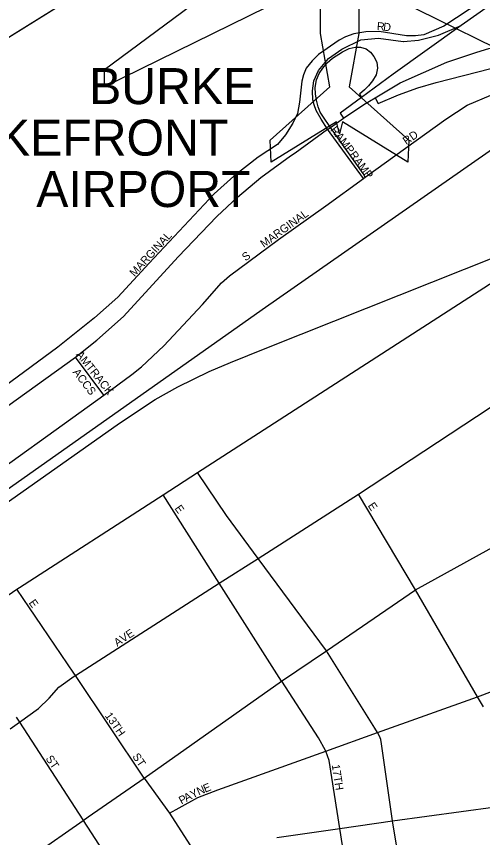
# Model space of a CAD drawing. Extents: x 2139079 to 2262683, y 1235796 to 1334992.
# Drawn here: x 2191123 to 2194033, y 1277243 to 1282370 of the extents above; entities that cross this region are included whole.
import ezdxf

# ---------------------------------------------------------------- set-up
doc = ezdxf.new("R2010")
doc.units = 0
for name, color, linetype in [('GM_X_Airport_Class_1', 7, 'Continuous'), ('GM_X_Airport_Text_Class_1', 7, 'Continuous'), ('GM_X_City_Street', 7, 'Continuous'), ('GM_X_City_Street_Text', 7, 'Continuous'), ('GM_X_Interchange_Ramps', 7, 'Continuous'), ('GM_X_Interstate_Route', 7, 'Continuous'), ('GM_X_Major_Lake', 7, 'Continuous'), ('GM_X_Rail_Line', 7, 'Continuous'), ('GM_X_State_Route', 7, 'Continuous'), ('GM_X_US_Route', 7, 'Continuous')]:
    doc.layers.add(name, color=color, linetype=linetype)

msp = doc.modelspace()

# ---------------------------------------------------------------- linework, layer by layer
at = {"layer": 'GM_X_Airport_Class_1'}
for points in [[(2193140.2, 1281637.8), (2193121.4, 1281711.9), (2192713.4, 1281459), (2192707.5, 1281596.6), (2193080.1, 1281930.7), (2193020, 1282263.2), (2193020, 1282593.4), (2191673.7, 1281929.9), (2191673.7, 1282039.4), (2192209.1, 1282435.3)], [(2194071.4, 1282435.3), (2194606.8, 1282039.4), (2194606.8, 1281929.9), (2193260.5, 1282593.4), (2193260.5, 1282263.2), (2193200.4, 1281930.7), (2193572.9, 1281596.6), (2193567.1, 1281459), (2193159, 1281711.9), (2193140.2, 1281637.8)]]:
    msp.add_lwpolyline(points, dxfattribs=at)
at = {"layer": 'GM_X_City_Street'}
for points in [[(2193289.3, 1281359), (2193299.7, 1281367.3), (2193552, 1281546.9), (2193802.9, 1281728.2), (2193935.7, 1281815.7), (2194084.6, 1281878.9), (2194378.3, 1281974.7), (2194463.9, 1282006.1), (2194512.4, 1282028.8), (2194561, 1282051.6), (2194694.7, 1282130.5), (2194996.1, 1282346.7), (2195257.9, 1282550.9), (2195383.5, 1282693.6), (2195668, 1283075.6), (2195903.1, 1283394.7), (2196027, 1283536.1), (2196119.5, 1283633.9), (2196406.7, 1283843.3), (2197904.1, 1284893.8)], [(2194028, 1282464.6), (2193791.3, 1282310.1), (2193665.2, 1282256), (2193614.3, 1282248.3), (2193557.1, 1282248.3), (2193387.2, 1282276.6), (2193303.9, 1282273.7), (2193229.2, 1282261.4), (2193177.5, 1282241.7), (2193138.1, 1282221.1), (2193008.9, 1282132.5), (2192968.9, 1282092.2), (2192931.5, 1282046.6), (2192913.9, 1282005.9), (2192904, 1281965.7), (2192888.9, 1281834.7), (2192877.3, 1281764.1), (2192847.8, 1281703.3), (2192803.5, 1281631), (2192752.5, 1281570.2), (2192632.7, 1281491.4), (2192479.5, 1281373.3), (2192356.3, 1281262), (2191951.6, 1280829.3), (2191755.3, 1280618), (2191609.8, 1280487.1), (2191381.7, 1280304.3), (2191048.3, 1280060)], [(2193539.5, 1282213.3), (2193631.9, 1282220.7), (2193756.7, 1282252.1), (2193898.6, 1282312.3)], [(2193289.3, 1281359), (2193065.3, 1281665), (2193024.3, 1281728), (2192994.7, 1281783.2), (2192981.2, 1281817.6), (2192972.3, 1281850.1), (2192971.5, 1281905), (2192978.6, 1281968.2), (2193007.5, 1282031.9), (2193071.9, 1282107.4), (2193153.3, 1282166), (2193271.8, 1282223), (2193383.6, 1282234.6), (2193536.3, 1282213.1), (2193539.5, 1282213.3)], [(2191475.2, 1279865.9), (2191669.4, 1280004.8), (2191844.2, 1280134.5), (2191903.5, 1280181.6), (2192042.6, 1280312.8), (2192283.9, 1280570.6), (2192404.1, 1280706.9), (2192452.6, 1280751.2), (2192759.3, 1280976.7), (2193054.8, 1281188.3), (2193289.3, 1281359)], [(2191143.3, 1278804.7), (2192038.6, 1279382.6), (2192253.8, 1279521.5), (2194362.9, 1280882.8)], [(2191484.2, 1278250.3), (2191491.2, 1278255.1), (2192389.5, 1278830.9), (2192631.9, 1278986.3), (2193257.9, 1279387.5), (2194159.3, 1279980.2), (2194716.7, 1280330.3), (2195137.4, 1280604.8), (2195175.8, 1280629.9), (2195293.5, 1280703), (2195567.4, 1280882.4)], [(2192078.6, 1277394.3), (2192139, 1277429.1), (2192255.8, 1277493.6), (2192381.1, 1277540.8), (2193054.4, 1277782.2), (2193377.5, 1277898), (2194000, 1278121.1), (2195091.4, 1278534.1), (2195674.4, 1278761.3), (2196370.6, 1279030.8), (2198889.4, 1280010.3), (2200879.8, 1280784.3)], [(2191669.4, 1280004.8), (2191491, 1280241.7)], [(2190067.4, 1278886.8), (2190180.5, 1278965), (2190501.9, 1279181.6), (2190975, 1279508.2), (2191475.2, 1279865.9)], [(2192631.9, 1278986.3), (2192435.2, 1279252.9), (2192253.8, 1279521.5)], [(2192778.8, 1278218.7), (2192778.4, 1278219.4), (2192389.5, 1278830.9), (2192038.6, 1279382.6)], [(2194037.4, 1278058.4), (2194000, 1278121.1), (2193613.8, 1278789.6), (2193257.9, 1279387.5)], [(2193100.7, 1278341.1), (2193058.9, 1278407.8), (2192631.9, 1278986.3)], [(2188798.9, 1277219.2), (2189624.1, 1277765.3), (2190085.9, 1278103.7), (2190750.5, 1278535.1), (2191125.4, 1278793.1), (2191143.3, 1278804.7)], [(2191481, 1278270), (2191125.4, 1278793.1)], [(2193771.5, 1275210.6), (2193775.7, 1275255.6), (2193780.2, 1275329.9), (2193778.7, 1275350.1), (2193770.9, 1275448.5), (2193694.2, 1275932), (2193670.2, 1276092.5), (2193597, 1276581.1), (2193469.6, 1277346.7), (2193402.6, 1277828.5), (2193397.8, 1277854.2), (2193390, 1277876.6), (2193377.5, 1277898), (2193360.8, 1277926.4), (2193100.7, 1278341.1)], [(2191083.8, 1277921.3), (2191141.9, 1277963.2), (2191259.9, 1278048.2), (2191327.4, 1278112.6), (2191387, 1278182.8), (2191484.2, 1278250.3)], [(2191921.2, 1277613.3), (2191491.2, 1278255.1), (2191481, 1278270)], [(2193141.7, 1277299.4), (2193075.2, 1277723.5), (2193054.4, 1277782.2), (2193053.2, 1277785.6), (2193009.1, 1277865.7), (2192778.8, 1278218.7)], [(2191120.8, 1277994), (2191141.9, 1277963.2), (2191537.6, 1277352.6)], [(2191537.6, 1277352.6), (2191539.9, 1277349.1), (2191834.9, 1276894.1)], [(2193262.9, 1276526.3), (2193141.7, 1277299.4)]]:
    msp.add_lwpolyline(points, dxfattribs=at)
at = {"layer": 'GM_X_Interchange_Ramps'}
for points in [[(2194741.1, 1282815.3), (2194699.3, 1282873.7), (2194248.3, 1282561.3), (2193898.6, 1282312.3), (2193475.2, 1282009.3), (2193277, 1281863.5), (2193144.2, 1281765.9), (2193164.5, 1281733.7)], [(2193299.7, 1281367.3), (2193287.2, 1281388.8), (2193083.5, 1281676), (2193035.2, 1281747), (2193019.5, 1281771.2), (2193006.8, 1281805.3), (2192996.8, 1281846.5), (2192989.7, 1281886.3), (2192988.3, 1281926.1), (2192996.8, 1281974.4), (2193012.6, 1282013.8), (2193034.8, 1282047.5), (2193062.7, 1282080.1), (2193096.1, 1282109.8), (2193159.3, 1282149.8), (2193200.8, 1282169.9), (2193238.3, 1282178.9), (2193271, 1282177.8), (2193306, 1282168.3), (2193332.8, 1282146.4), (2193353.9, 1282120.6), (2193372.1, 1282084.3), (2193376.1, 1282046.8), (2193369.3, 1282005.2), (2193346.4, 1281967.7), (2193319.6, 1281935.9), (2193295.4, 1281912.5), (2193263.6, 1281884.9), (2193277, 1281863.5)], [(2193361.5, 1281862.5), (2193380.8, 1281825.6), (2193507, 1281880.8), (2193627.7, 1281924), (2193743.3, 1281956.9), (2194336.8, 1282108.6), (2194393, 1282114.3), (2194424.6, 1282110.1), (2194457.7, 1282098), (2194485.5, 1282069.1), (2194512.4, 1282028.8), (2194527.1, 1282007), (2194571.9, 1282035.8)]]:
    msp.add_lwpolyline(points, dxfattribs=at)
at = {"layer": 'GM_X_Interstate_Route'}
msp.add_lwpolyline([(2189760.3, 1281423.6), (2195942.9, 1285269.6)], dxfattribs=at)
at = {"layer": 'GM_X_Major_Lake'}
msp.add_lwpolyline([(2189764.7, 1281426.2), (2195947.3, 1285272.1), (2196057.6, 1285267), (2196083.9, 1285284.2)], dxfattribs=at)
at = {"layer": 'GM_X_Rail_Line'}
for points in [[(2188798.9, 1277974.5), (2189752.1, 1278588.8), (2190639.6, 1279116), (2192678, 1280555.1), (2194231.5, 1281639.3), (2194948.6, 1282154.6), (2195509, 1282554.5), (2195871.7, 1282810.1), (2196378.5, 1283156.3), (2197087.3, 1283630.4), (2199383.9, 1285076.5), (2199860.7, 1285394.8)], [(2188798.9, 1277881.4), (2189757.9, 1278481.3), (2190617.3, 1279020.4), (2191767.2, 1279829.6), (2191989.8, 1279978), (2192129.9, 1280056.3), (2192326.4, 1280152.7), (2192459.3, 1280209.9), (2192568.2, 1280252.3), (2192695.5, 1280304), (2194123.4, 1280872.7), (2194416.4, 1280986.7)]]:
    msp.add_lwpolyline(points, dxfattribs=at)
at = {"layer": 'GM_X_State_Route'}
for points in [[(2193997.2, 1282146.1), (2194071.1, 1282170.5), (2194152, 1282190.5)], [(2192862.8, 1281519), (2193065.3, 1281665), (2193070.8, 1281669), (2193083.5, 1281676), (2193164.5, 1281733.7), (2193290.9, 1281820.8), (2193361.5, 1281862.5), (2193518.1, 1281954.9), (2193809.1, 1282084.1), (2193997.2, 1282146.1)], [(2190881.9, 1279805.4), (2191491, 1280241.7), (2191624.5, 1280348.6), (2191791, 1280496.4), (2192133.4, 1280869.4), (2192373.6, 1281120.4), (2192502.1, 1281240.5), (2192649.6, 1281363.5), (2192834.7, 1281498.8), (2192862.8, 1281519)]]:
    msp.add_lwpolyline(points, dxfattribs=at)
at = {"layer": 'GM_X_US_Route'}
for points in [[(2191921.2, 1277613.3), (2192778.4, 1278219.4), (2193058.9, 1278407.8), (2193613.8, 1278789.6), (2194574.9, 1279320.4), (2195160, 1279631.1), (2195310.7, 1279716.9)], [(2191571.8, 1277371.2), (2191921.2, 1277613.3)], [(2191921.2, 1277613.3), (2192078.6, 1277394.3), (2192225.1, 1277167.3)], [(2192748.1, 1277242.7), (2193141.7, 1277299.4), (2193469.6, 1277346.7), (2194328.1, 1277463), (2194625.3, 1277504.8), (2194736.8, 1277520.8)], [(2190916.6, 1276917.3), (2191539.9, 1277349.1), (2191571.8, 1277371.2)]]:
    msp.add_lwpolyline(points, dxfattribs=at)

# ---------------------------------------------------------------- texts
at = {"layer": 'GM_X_Airport_Text_Class_1'}
for s, p in [('BURKE', (2191577, 1281822.2)), ('LAKEFRONT', (2190639.8, 1281501)), ('AIRPORT', (2191247, 1281179.8))]:
    msp.add_text(s, height=225, rotation=0, dxfattribs=at).set_placement(p)
at = {"layer": 'GM_X_City_Street_Text'}
for s, rotation, p in [('R', 355.551, (2193371.2, 1282284.9)), ('D', 353.4715, (2193410.2, 1282281.9)), ('RAMP', 307.7474, (2193079.9, 1281660.4)), ('RD', 34.505, (2193556.1, 1281566)), ('RAMP', 306.5698, (2193198.9, 1281506.3)), ('MARGINAL', 35.8036, (2192667.4, 1280923.7)), ('MARGINAL', 47.3667, (2191860.3, 1280741.7)), ('S', 35.5436, (2192552.7, 1280839.9)), ('AMTRACK', 308.5293, (2191492, 1280257.3)), ('ACCS', 307.1845, (2191472, 1280148)), ('E', 305.5436, (2192108.2, 1279297.7)), ('E', 303.6733, (2193314, 1279315.1)), ('E', 305.5436, (2191197.4, 1278708.1)), ('AVE', 33.6901, (2191752.2, 1278433.3)), ('13TH', 304.6965, (2191672.7, 1278004)), ('ST', 304.6908, (2191844.3, 1277748.8)), ('ST', 304.6987, (2191303.1, 1277735.6)), ('17TH', 278.8832, (2193091.1, 1277696.5)), ('N', 23.2589, (2192261, 1277505.3)), ('E', 22.8111, (2192301.4, 1277522.6)), ('P', 28.545, (2192153.3, 1277448.1)), ('A', 28.5494, (2192184.2, 1277464.9)), ('Y', 26.7508, (2192222.5, 1277485.8))]:
    msp.add_text(s, height=50, rotation=rotation, dxfattribs=at).set_placement(p)

doc.saveas('drawing.dxf')
